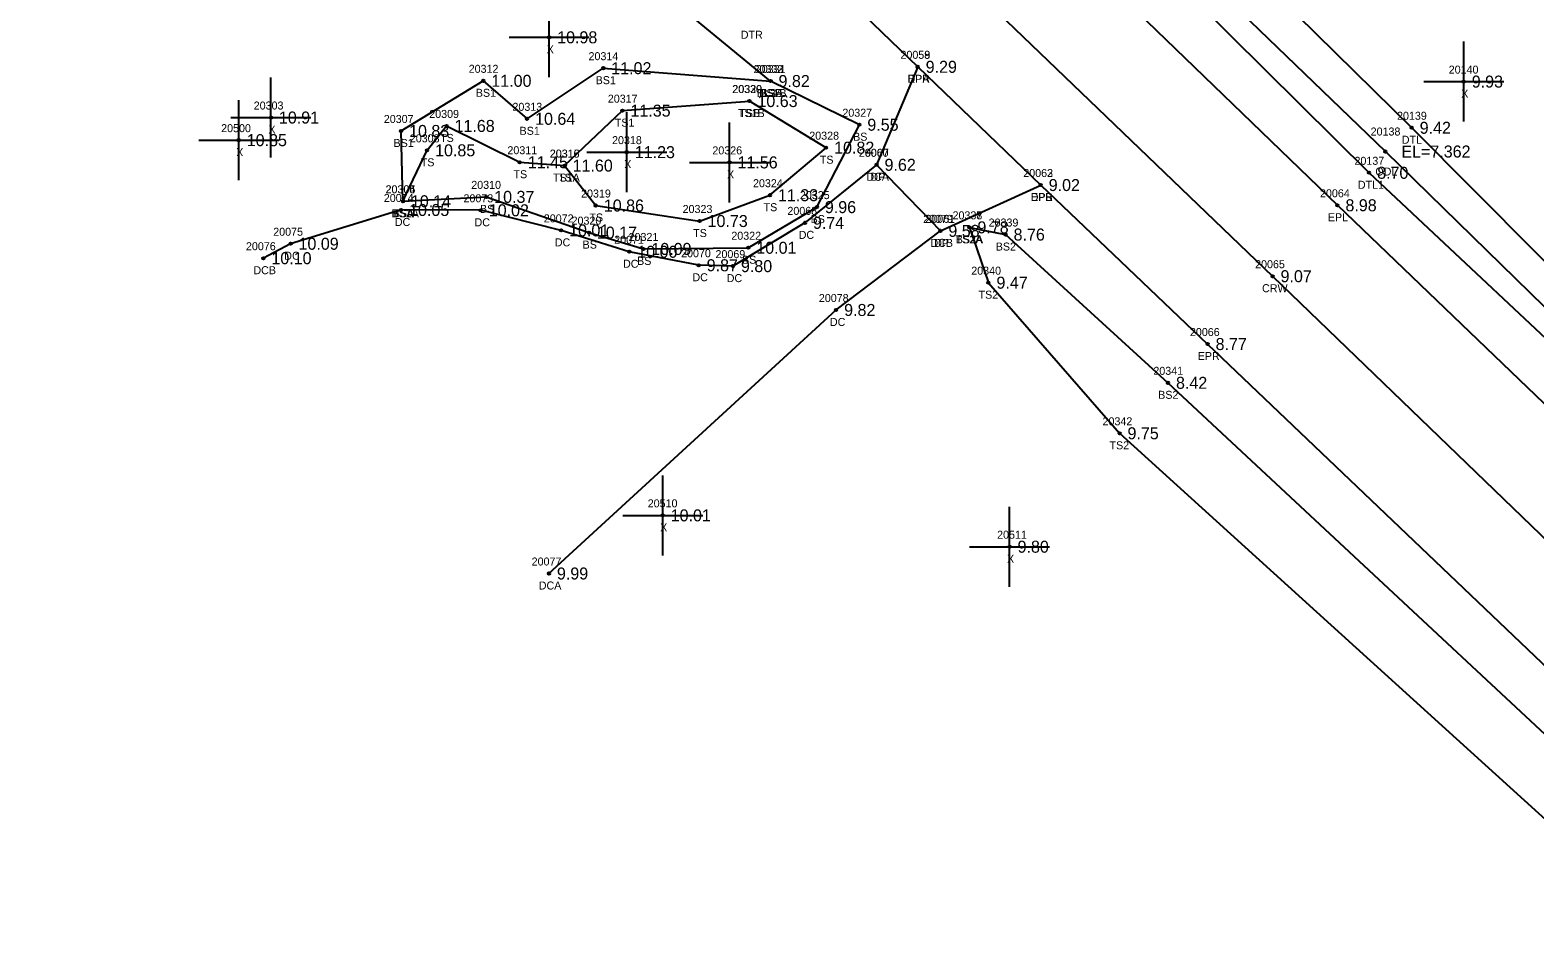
# Model space of a CAD drawing. Extents: x 2608745 to 2610333, y 641917 to 643463.
# Drawn here: x 2608806.9 to 2608995, y 643149.1 to 643262.1 of the extents above; entities that cross this region are included whole.
import ezdxf

# ---------------------------------------------------------------- set-up
doc = ezdxf.new("R2010")
doc.units = 0
for name, color, linetype in [('RD_DTM_BkLn1', 7, 'Continuous'), ('RD_DTM_BkLn2', 7, 'Continuous'), ('RD_DTM_BkLn_txCode', 7, 'Continuous'), ('RD_EX_Conc', 7, 'Continuous'), ('RD_EX_Conc_txCode', 7, 'Continuous'), ('RD_EX_Driveway', 7, 'Continuous'), ('RD_EX_Driveway_txCode', 7, 'Continuous'), ('RD_EX_H2O', 7, 'Continuous'), ('RD_EX_H2O_txCode', 7, 'Continuous'), ('RD_EX_Misc', 7, 'Continuous'), ('RD_EX_Misc_txCode', 7, 'Continuous'), ('RD_EX_Road', 7, 'Continuous'), ('RD_EX_Road_txCode', 7, 'Continuous'), ('RD_EX_TX_Conc_ELEV', 7, 'Continuous'), ('RD_EX_TX_Driveway_ELEV', 7, 'Continuous'), ('RD_EX_TX_H2O_ELEV', 7, 'Continuous'), ('RD_EX_TX_Misc_ELEV', 7, 'Continuous'), ('RD_EX_TX_Road_ELEV', 7, 'Continuous'), ('RD_HC_Survey_ELEV', 7, 'Continuous'), ('RD_HC_Survey_txCode', 7, 'Continuous'), ('RD_SMD_Locator', 7, 'Continuous')]:
    doc.layers.add(name, color=color, linetype=linetype)

msp = doc.modelspace()

# ---------------------------------------------------------------- linework, layer by layer
at = {"layer": 'RD_DTM_BkLn1'}
for points in [[(2608814.73, 643373.65), (2608890.45, 643300.26), (2608962.19, 643231.31), (2609034.91, 643161.19), (2609108.48, 643089.9), (2609179.19, 643022.29), (2609255.71, 642948.78), (2609335.19, 642871.73), (2609410.7, 642798.48), (2609491.67, 642719.95), (2609518.07, 642695.15)], [(2608899.44, 643255.71), (2608879.96, 643271.75), (2608867.99, 643283.69)]]:
    msp.add_lwpolyline(points, dxfattribs=at)
at = {"layer": 'RD_DTM_BkLn2'}
for points in [[(2608853.49, 643240.68), (2608853.26, 643249.47), (2608863.54, 643255.74), (2608869.01, 643250.99), (2608878.53, 643257.32), (2608899.44, 643255.71)], [(2608853.49, 643240.68), (2608863.9, 643241.23), (2608876.73, 643236.76), (2608883.54, 643234.72), (2608896.66, 643234.87), (2608905.23, 643239.95), (2608910.54, 643250.25), (2608899.44, 643255.71)], [(2608853.49, 643240.68), (2608856.51, 643247.05), (2608858.94, 643250.1), (2608868.1, 643245.56), (2608873.7, 643245.14), (2608877.6, 643240.15), (2608890.57, 643238.21), (2608899.37, 643241.44), (2608906.39, 643247.38), (2608896.8, 643253.21)], [(2608873.7, 643245.14), (2608880.93, 643252.01), (2608896.8, 643253.21)], [(2608924.3, 643237.42), (2608926.68, 643230.5), (2608943.06, 643211.67), (2609016.47, 643145.1), (2609020.37, 643138.12), (2609021.09, 643123.73), (2609015.67, 643117.4)], [(2608924.3, 643237.42), (2608928.82, 643236.52), (2608949.12, 643217.98), (2609021.97, 643150.06), (2609029.11, 643139.98), (2609031.81, 643128.97), (2609015.67, 643117.4)]]:
    msp.add_lwpolyline(points, dxfattribs=at)
at = {"layer": 'RD_EX_Conc'}
for points in [[(2608912.69, 643245.24), (2608903.74, 643237.98), (2608894.74, 643232.57), (2608890.46, 643232.68), (2608881.78, 643234.37), (2608873.26, 643237.04), (2608863.22, 643239.55), (2608853.26, 643239.59), (2608839.44, 643235.37), (2608836.05, 643233.56)], [(2608871.74, 643194.14), (2608907.64, 643227.09), (2608920.67, 643236.98)]]:
    msp.add_lwpolyline(points, dxfattribs=at)
at = {"layer": 'RD_EX_Driveway'}
msp.add_lwpolyline([(2608917.83, 643257.49), (2608912.69, 643245.24), (2608920.67, 643236.98), (2608933.21, 643242.71)], dxfattribs=at)
at = {"layer": 'RD_EX_H2O'}
for points in [[(2608906.46, 643316.31), (2608904.96, 643314.36), (2608904.5, 643312.12), (2608909.12, 643308.85), (2608974.26, 643244.24), (2609005.73, 643214.72), (2609009.05, 643211.6), (2609010.84, 643213.4), (2609012.56, 643215.9), (2609010.65, 643218.64)], [(2608906.46, 643316.31), (2608908.31, 643316.67), (2608911.14, 643317.04), (2608914.89, 643313.48), (2608979.58, 643249.87), (2609010.65, 643218.64)], [(2608907.36, 643312.77), (2608910.89, 643309.96), (2608976.29, 643246.9), (2609008.79, 643215.13)]]:
    msp.add_lwpolyline(points, dxfattribs=at)
at = {"layer": 'RD_EX_Misc'}
for p, q in [((2608871.77, 643256.18), (2608871.77, 643266.18)), ((2608866.77, 643261.18), (2608876.77, 643261.18)), ((2608986.09, 643250.64), (2608986.09, 643260.64)), ((2608836.99, 643246.15), (2608836.99, 643256.15)), ((2608981.09, 643255.64), (2608991.09, 643255.64)), ((2608832.97, 643243.32), (2608832.97, 643253.32)), ((2608831.99, 643251.15), (2608841.99, 643251.15)), ((2608881.47, 643241.82), (2608881.47, 643251.82)), ((2608894.31, 643240.54), (2608894.31, 643250.54)), ((2608827.97, 643248.32), (2608837.97, 643248.32)), ((2608876.47, 643246.82), (2608886.47, 643246.82)), ((2608889.31, 643245.54), (2608899.31, 643245.54)), ((2608885.96, 643196.41), (2608885.96, 643206.41)), ((2608880.96, 643201.41), (2608890.96, 643201.41)), ((2608929.32, 643192.49), (2608929.32, 643202.49)), ((2608924.32, 643197.49), (2608934.32, 643197.49))]:
    msp.add_line(p, q, dxfattribs=at)
at = {"layer": 'RD_EX_Road'}
for points in [[(2608823.57, 643381.9), (2608829.58, 643376.81), (2608846.19, 643359.9), (2608852.07, 643354.1), (2608873.12, 643334.61), (2608877.91, 643330.13), (2608897.26, 643311.51), (2608898.77, 643309.3), (2608970.3, 643240.18), (2609042.49, 643170.94), (2609058.51, 643155.46), (2609096.06, 643119.37)], [(2608806.89, 643364.99), (2608810.18, 643361.1), (2608820.75, 643351.25), (2608881.81, 643292.24), (2608917.83, 643257.49), (2608933.21, 643242.71), (2608954.07, 643222.83), (2609026.06, 643154.19), (2609039.6, 643139.96), (2609073.88, 643106.95), (2609100.48, 643081.89), (2609124.19, 643058.87), (2609171.61, 643013.71), (2609183.19, 643002.28), (2609197.91, 642988.37), (2609247.59, 642940.95), (2609328.02, 642863.6), (2609402.61, 642790.3), (2609474.23, 642720.69), (2609483.84, 642711.58), (2609495.78, 642699.92), (2609509.81, 642686.45)]]:
    msp.add_lwpolyline(points, dxfattribs=at)
at = {"layer": 'RD_SMD_Locator'}
for centre in [(2608871.77, 643261.18), (2608917.83, 643257.49), (2608917.83, 643257.49), (2608863.54, 643255.74), (2608878.53, 643257.32), (2608899.44, 643255.71), (2608899.44, 643255.71), (2608899.44, 643255.71), (2608986.09, 643255.64), (2608880.93, 643252.01), (2608896.8, 643253.21), (2608896.8, 643253.21), (2608836.99, 643251.15), (2608858.94, 643250.1), (2608869.01, 643250.99), (2608910.54, 643250.25), (2608979.58, 643249.87), (2608832.97, 643248.32), (2608853.26, 643249.47), (2608856.51, 643247.05), (2608881.47, 643246.82), (2608906.39, 643247.38), (2608976.29, 643246.9), (2608868.1, 643245.56), (2608873.7, 643245.14), (2608873.7, 643245.14), (2608894.31, 643245.54), (2608912.69, 643245.24), (2608912.69, 643245.24), (2608974.26, 643244.24), (2608933.21, 643242.71), (2608933.21, 643242.71), (2608853.49, 643240.68), (2608853.49, 643240.68), (2608853.49, 643240.68), (2608863.9, 643241.23), (2608899.37, 643241.44), (2608853.26, 643239.59), (2608863.22, 643239.55), (2608877.6, 643240.15), (2608905.23, 643239.95), (2608970.3, 643240.18), (2608873.26, 643237.04), (2608876.73, 643236.76), (2608890.57, 643238.21), (2608903.74, 643237.98), (2608920.67, 643236.98), (2608920.67, 643236.98), (2608924.3, 643237.42), (2608924.3, 643237.42), (2608839.44, 643235.37), (2608896.66, 643234.87), (2608928.82, 643236.52), (2608836.05, 643233.56), (2608881.78, 643234.37), (2608883.54, 643234.72), (2608890.46, 643232.68), (2608894.74, 643232.57), (2608962.19, 643231.31), (2608926.68, 643230.5), (2608907.64, 643227.09), (2608954.07, 643222.83), (2608949.12, 643217.98), (2608943.06, 643211.67), (2608885.96, 643201.41), (2608929.32, 643197.49), (2608871.74, 643194.14)]:
    msp.add_circle(centre, 0.15, dxfattribs=at)

# ---------------------------------------------------------------- texts
at = {"layer": 'RD_DTM_BkLn_txCode'}
for s, p in [('20312', (2608861.71, 643256.74)), ('20314', (2608876.69, 643258.32)), ('20332', (2608897.32, 643256.71)), ('20333', (2608897.32, 643256.71)), ('20331', (2608897.6, 643256.71)), ('BS1', (2608877.58, 643255.32)), ('BS1', (2608862.6, 643253.74)), ('20317', (2608879.1, 643253.01)), ('20330', (2608894.64, 643254.21)), ('20329', (2608894.68, 643254.21)), ('BL3A', (2608897.74, 643253.71)), ('BS1B', (2608898.02, 643253.71)), ('BSB', (2608898.19, 643253.71)), ('20309', (2608856.78, 643251.1)), ('20313', (2608867.18, 643251.99)), ('TS1B', (2608895.37, 643251.21)), ('TSB', (2608895.53, 643251.21)), ('20327', (2608908.42, 643251.25)), ('20307', (2608851.1, 643250.47)), ('TS1', (2608879.97, 643250.01)), ('BS1', (2608852.31, 643247.47)), ('20308', (2608854.35, 643248.05)), ('TS', (2608858.14, 643248.1)), ('BS1', (2608868.07, 643248.99)), ('20328', (2608904.28, 643248.38)), ('BS', (2608909.76, 643248.25)), ('20311', (2608866.55, 643246.56)), ('20316', (2608871.84, 643246.14)), ('20315', (2608871.86, 643246.14)), ('TS', (2608905.6, 643245.38)), ('TS', (2608855.72, 643245.05)), ('TS', (2608867.31, 643243.56)), ('20306', (2608851.31, 643241.68)), ('20304', (2608851.33, 643241.68)), ('20305', (2608851.33, 643241.68)), ('20310', (2608862.03, 643242.23)), ('TS1A', (2608872.25, 643243.14)), ('TS', (2608872.9, 643243.14)), ('20324', (2608897.25, 643242.44)), ('20319', (2608875.76, 643241.15)), ('20325', (2608903.11, 643240.95)), ('BS1A', (2608852.06, 643238.68)), ('TSA', (2608852.21, 643238.68)), ('BSA', (2608852.22, 643238.68)), ('BS', (2608863.12, 643239.23)), ('20320', (2608874.57, 643237.76)), ('TS', (2608876.8, 643238.15)), ('20323', (2608888.45, 643239.21)), ('TS', (2608898.57, 643239.44)), ('BS', (2608904.45, 643237.95)), ('20337', (2608922.19, 643238.42)), ('20338', (2608922.19, 643238.42)), ('TS', (2608889.77, 643236.21)), ('20322', (2608894.54, 643235.87)), ('20339', (2608926.7, 643237.52)), ('BS', (2608875.95, 643234.76)), ('20321', (2608881.7, 643235.72)), ('TS2A', (2608922.57, 643235.42)), ('BS2A', (2608922.59, 643235.42)), ('BS2', (2608927.59, 643234.52)), ('BS', (2608882.76, 643232.72)), ('BS', (2608895.88, 643232.87)), ('20340', (2608924.53, 643231.5)), ('TS2', (2608925.44, 643228.5)), ('20341', (2608947.29, 643218.98)), ('BS2', (2608947.89, 643215.98)), ('20342', (2608940.94, 643212.67)), ('TS2', (2608941.81, 643209.67))]:
    msp.add_text(s, height=1, dxfattribs=at).set_placement(p)
at = {"layer": 'RD_EX_Conc_txCode'}
for s, p in [('20067', (2608910.5, 643246.24)), ('DCA', (2608911.42, 643243.24)), ('20074', (2608851.1, 643240.59)), ('20073', (2608861.06, 643240.55)), ('20072', (2608871.1, 643238.04)), ('20068', (2608901.55, 643238.98)), ('20079', (2608918.52, 643237.98)), ('20075', (2608837.28, 643236.37)), ('DC', (2608852.48, 643237.59)), ('DC', (2608862.44, 643237.55)), ('DC', (2608902.96, 643235.98)), ('20076', (2608833.87, 643234.56)), ('DC', (2608872.48, 643235.04)), ('20071', (2608879.9, 643235.37)), ('DCB', (2608919.42, 643234.98)), ('DC', (2608838.66, 643233.37)), ('DC', (2608881, 643232.37)), ('20070', (2608888.26, 643233.68)), ('20069', (2608892.56, 643233.57)), ('DCB', (2608834.8, 643231.56)), ('DC', (2608889.68, 643230.68)), ('DC', (2608893.96, 643230.57)), ('20078', (2608905.48, 643228.09)), ('DC', (2608906.86, 643225.09)), ('20077', (2608869.58, 643195.14)), ('DCA', (2608870.47, 643192.14))]:
    msp.add_text(s, height=1, dxfattribs=at).set_placement(p)
at = {"layer": 'RD_EX_Driveway_txCode'}
for s, p in [('20059', (2608915.68, 643258.49)), ('DPA', (2608916.56, 643255.49)), ('20060', (2608910.47, 643246.24)), ('20062', (2608931.03, 643243.71)), ('DP', (2608911.91, 643243.24)), ('DPB', (2608931.96, 643240.71)), ('20061', (2608918.78, 643237.98)), ('DP', (2608919.89, 643234.98))]:
    msp.add_text(s, height=1, dxfattribs=at).set_placement(p)
at = {"layer": 'RD_EX_H2O_txCode'}
for s, p in [('DTR', (2608895.72, 643261)), ('20139', (2608977.75, 643250.87)), ('20138', (2608974.45, 643248.9)), ('DTL', (2608978.34, 643247.87)), ('20137', (2608972.43, 643245.24)), ('ODL', (2608975.04, 643243.9)), ('DTL1', (2608972.85, 643242.24))]:
    msp.add_text(s, height=1, dxfattribs=at).set_placement(p)
at = {"layer": 'RD_EX_Misc_txCode'}
for s, p in [('X', (2608871.46, 643259.18)), ('20140', (2608984.21, 643256.64)), ('X', (2608985.77, 643253.64)), ('20303', (2608834.84, 643252.15)), ('20500', (2608830.77, 643249.32)), ('X', (2608836.68, 643249.15)), ('20318', (2608879.63, 643247.82)), ('X', (2608832.65, 643246.32)), ('20326', (2608892.17, 643246.54)), ('X', (2608881.15, 643244.82)), ('X', (2608894, 643243.54)), ('20510', (2608884.09, 643202.41)), ('X', (2608885.64, 643199.41)), ('20511', (2608927.76, 643198.49)), ('X', (2608929, 643195.49))]:
    msp.add_text(s, height=1, dxfattribs=at).set_placement(p)
at = {"layer": 'RD_EX_Road_txCode'}
for s, p in [('20058', (2608915.68, 643258.49)), ('EPR', (2608916.6, 643255.49)), ('20063', (2608931.03, 643243.71)), ('EPR', (2608931.98, 643240.71)), ('20064', (2608968.12, 643241.18)), ('EPL', (2608969.1, 643238.18)), ('20066', (2608951.86, 643223.83)), ('EPR', (2608952.84, 643220.83))]:
    msp.add_text(s, height=1, dxfattribs=at).set_placement(p)
at = {"layer": 'RD_EX_TX_Conc_ELEV'}
for s, p in [('9.62', (2608913.69, 643244.49)), ('10.05', (2608854.26, 643238.84)), ('10.02', (2608864.22, 643238.8)), ('9.74', (2608904.74, 643237.23)), ('10.01', (2608874.26, 643236.29)), ('9.58', (2608921.67, 643236.23)), ('10.09', (2608840.44, 643234.62)), ('10.00', (2608882.78, 643233.62)), ('10.10', (2608837.05, 643232.81)), ('9.87', (2608891.46, 643231.93)), ('9.80', (2608895.74, 643231.82)), ('9.82', (2608908.64, 643226.34)), ('9.99', (2608872.74, 643193.39))]:
    msp.add_text(s, height=1.5, dxfattribs=at).set_placement(p)
at = {"layer": 'RD_EX_TX_Driveway_ELEV'}
for s, p in [('9.29', (2608918.83, 643256.74)), ('9.62', (2608913.69, 643244.49)), ('9.02', (2608934.21, 643241.96)), ('9.58', (2608921.67, 643236.23))]:
    msp.add_text(s, height=1.5, dxfattribs=at).set_placement(p)
at = {"layer": 'RD_EX_TX_H2O_ELEV'}
for s, p in [('9.42', (2608980.58, 643249.12)), ('EL=7.362', (2608978.29, 643246.15)), ('8.70', (2608975.26, 643243.49))]:
    msp.add_text(s, height=1.5, dxfattribs=at).set_placement(p)
at = {"layer": 'RD_EX_TX_Misc_ELEV'}
for s, p in [('10.98', (2608872.77, 643260.43)), ('11.02', (2608879.53, 643256.57)), ('11.00', (2608864.54, 643254.99)), ('9.82', (2608900.44, 643254.96)), ('9.82', (2608900.44, 643254.96)), ('9.82', (2608900.44, 643254.96)), ('9.93', (2608987.09, 643254.89)), ('10.63', (2608897.8, 643252.46)), ('10.63', (2608897.8, 643252.46)), ('10.91', (2608837.99, 643250.4)), ('11.35', (2608881.93, 643251.26)), ('10.83', (2608854.26, 643248.72)), ('11.68', (2608859.94, 643249.35)), ('10.64', (2608870.01, 643250.24)), ('9.55', (2608911.54, 643249.5)), ('10.85', (2608833.97, 643247.57)), ('10.82', (2608907.39, 643246.63)), ('10.85', (2608857.51, 643246.3)), ('11.45', (2608869.1, 643244.81)), ('11.23', (2608882.47, 643246.07)), ('11.56', (2608895.31, 643244.79)), ('11.60', (2608874.7, 643244.39)), ('11.60', (2608874.7, 643244.39)), ('10.14', (2608854.49, 643239.93)), ('10.14', (2608854.49, 643239.93)), ('10.14', (2608854.49, 643239.93)), ('10.37', (2608864.9, 643240.48)), ('10.86', (2608878.6, 643239.4)), ('11.33', (2608900.37, 643240.69)), ('9.96', (2608906.23, 643239.2)), ('10.73', (2608891.57, 643237.46)), ('10.17', (2608877.73, 643236.01)), ('9.78', (2608925.3, 643236.67)), ('9.78', (2608925.3, 643236.67)), ('8.76', (2608929.82, 643235.77)), ('10.09', (2608884.54, 643233.97)), ('10.01', (2608897.66, 643234.12)), ('9.47', (2608927.68, 643229.75)), ('8.42', (2608950.12, 643217.23)), ('9.75', (2608944.06, 643210.92)), ('10.01', (2608886.96, 643200.66)), ('9.80', (2608930.32, 643196.74))]:
    msp.add_text(s, height=1.5, dxfattribs=at).set_placement(p)
at = {"layer": 'RD_EX_TX_Road_ELEV'}
for s, p in [('9.29', (2608918.83, 643256.74)), ('9.02', (2608934.21, 643241.96)), ('8.98', (2608971.3, 643239.43)), ('8.77', (2608955.07, 643222.08))]:
    msp.add_text(s, height=1.5, dxfattribs=at).set_placement(p)
at = {"layer": 'RD_HC_Survey_ELEV'}
msp.add_text('9.07', height=1.5, dxfattribs=at).set_placement((2608963.19, 643230.56))
at = {"layer": 'RD_HC_Survey_txCode'}
for s, p in [('20065', (2608960.01, 643232.31)), ('CRW', (2608960.88, 643229.31))]:
    msp.add_text(s, height=1, dxfattribs=at).set_placement(p)

doc.saveas('drawing.dxf')
